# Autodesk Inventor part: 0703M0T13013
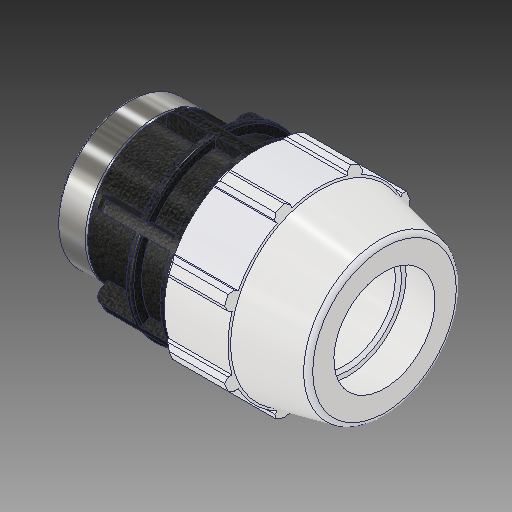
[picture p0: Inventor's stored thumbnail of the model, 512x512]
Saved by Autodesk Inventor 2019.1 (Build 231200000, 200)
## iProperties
Created: 2017-02
Part Number: 0703M0T13013
Material: PVC-Piping
Description: PLASSON FEMALE ADAPTOR G 1 1/4'' - 1 1/4''F
Document SubType Name: Modeling
Designer: KIM
Mass: 92.6774 g
Surface Area: 199.44 cm^2
Volume: 66.1981 cm^3
Density: 1.4 g/cm^3
Appearance: PTFE
Author: KIM
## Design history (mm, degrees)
derived "0703M0T.ipt"
feature "Solid1::0703M0T.ipt"
tag "TaggingFeature1"
body "Solid1"
other parameters: "d2" = 42.1, "d4" = 15.27629, "d5" = 26.7335, "d7" = 82.042, "d9" = 15.27629, "d11" = 3.05526, "d12" = 65.6336, "d13" = 120 deg, "d14" = 63.15, "d15" = 12 deg, "d16" = 73.8378, "d18" = 2.105, "d19" = 35 deg, "d20" = 17.5 deg, "d21" = 76.29906, "d23" = 0, "d25" = 360 deg, "d27" = 1.64084, "d34" = 4.1021, "d35" = 32.0802, "d36" = 0, "d42" = 26.7335, "d43" = 2.46126, "d46" = 1.263, "d49" = 76.962, "d51" = 106.934, "d53" = 0.842, "d55" = 360 deg, "d61" = 24.892, "d62" = 39.995, "d63" = 38.952, "d64" = 35.64467, "d65" = 4.1021, "d66" = 0.5, "d67" = 1, "d68" = 12.446, "d69" = 59.07024, "d70" = 1.27, "d_" = 42.1, "E_" = 82.042, "H_" = 106.934, "l_" = 76.962, "l_2" = 24.892, "G_" = 38.952
